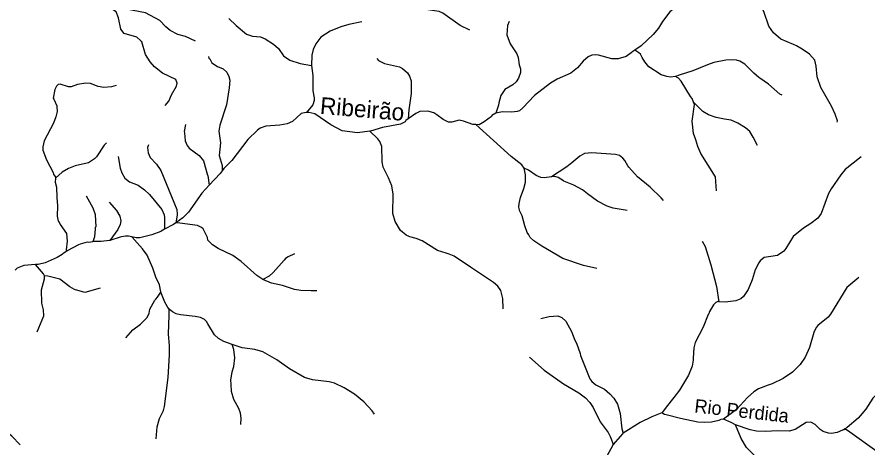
# Model space of a CAD drawing. Extents: x 280.4 to 335.6, y 8893.9 to 8949.5.
# Drawn here: x 314.12 to 324.16, y 8938.13 to 8943.22 of the extents above; entities that cross this region are included whole.
import ezdxf
from ezdxf.enums import TextEntityAlignment as Align

# ---------------------------------------------------------------- set-up
doc = ezdxf.new("R2010")
doc.units = 0
doc.header["$LTSCALE"] = 0.064
doc.layers.add('61', color=7, linetype='Continuous')
doc.layers.add('7', color=7, linetype='Continuous', lineweight=25)

msp = doc.modelspace()

# ---------------------------------------------------------------- linework, layer by layer
at = {"layer": '7'}
for p, q in [((318.2905, 8941.869), (318.2847, 8941.8682)), ((321.1556, 8938.1677), (321.0782, 8938.0222))]:
    msp.add_line(p, q, dxfattribs=at)
for points in [[(319.4625, 8943.0629), (319.3518, 8943.1173), (319.1473, 8943.2634), (319.1022, 8943.2832), (318.9404, 8943.3071), (318.7025, 8943.4163), (318.5373, 8943.5115), (318.373, 8943.6324), (318.2894, 8943.7208), (318.231, 8943.8085), (318.1513, 8943.983), (318.0958, 8944.0646), (318.0478, 8944.1159), (317.9296, 8944.1715), (317.8394, 8944.2139), (317.7235, 8944.2382), (317.638, 8944.2668), (317.5637, 8944.3067), (317.4833, 8944.3597), (317.3938, 8944.4325), (317.339, 8944.4902), (317.2758, 8944.5371), (317.1869, 8944.5672), (317.1169, 8944.5733)], [(322.6434, 8943.6376), (322.6119, 8943.6257), (322.3545, 8943.5073), (322.2424, 8943.4828), (322.1242, 8943.4758), (322.0597, 8943.4596), (321.9757, 8943.3812), (321.86, 8943.3071), (321.8269, 8943.2788), (321.7395, 8943.1632), (321.6899, 8943.0842), (321.6293, 8943.0127), (321.4863, 8942.8786), (321.4133, 8942.8255)], [(323.8022, 8941.9733), (323.8031, 8941.989), (323.7758, 8942.0709), (323.7336, 8942.1648), (323.6086, 8942.3833), (323.5647, 8942.5098), (323.5519, 8942.6364), (323.5385, 8942.7064), (323.4744, 8942.7782), (323.3888, 8942.837), (323.3192, 8942.8762), (323.2872, 8942.8942), (323.1369, 8942.9566), (323.0483, 8943.029), (322.9955, 8943.1073), (322.9365, 8943.2824), (322.8647, 8943.4233), (322.7805, 8943.5268), (322.7373, 8943.5683), (322.6434, 8943.6376)], [(315.8656, 8942.1736), (315.9103, 8942.2247), (315.9433, 8942.2985), (316.0031, 8942.4007), (316.0096, 8942.4356), (315.9942, 8942.4776), (315.8362, 8942.552), (315.7422, 8942.6281), (315.6891, 8942.6896), (315.6344, 8942.774), (315.5908, 8942.9225), (315.5797, 8942.9304), (315.5772, 8942.9417), (315.5316, 8942.9777), (315.384, 8943.022), (315.3445, 8943.0745), (315.3159, 8943.2089), (315.2875, 8943.2772), (315.2205, 8943.3235)], [(316.2248, 8942.9325), (316.1083, 8942.986), (316.0188, 8943.01), (315.9273, 8943.0573), (315.8761, 8943.102), (315.8046, 8943.1779), (315.6348, 8943.2664), (315.4054, 8943.3088), (315.3485, 8943.3361), (315.3039, 8943.3541)], [(316.6187, 8943.2005), (316.7038, 8943.1153), (316.8267, 8943.0132), (316.9, 8942.9893), (316.9934, 8942.9851), (317.0488, 8942.9589), (317.1475, 8942.8973), (317.2056, 8942.8455), (317.2658, 8942.7583), (317.3411, 8942.7088), (317.4599, 8942.6662), (317.5937, 8942.6439)], [(318.1879, 8943.1595), (318.0377, 8943.1295), (317.9411, 8943.1006), (317.8163, 8943.0508), (317.7071, 8942.9797), (317.6453, 8942.9023), (317.6142, 8942.8328), (317.5996, 8942.7667), (317.5937, 8942.6439)], [(319.9277, 8943.1661), (319.9093, 8943.1169), (319.9028, 8943.0058), (319.9401, 8942.9007), (320.021, 8942.7836), (320.0351, 8942.7394), (320.0478, 8942.6513), (320.0608, 8942.6051), (320.0624, 8942.5603), (320.0375, 8942.4945), (320.0096, 8942.4516), (319.9701, 8942.4168), (319.8789, 8942.3608), (319.8309, 8942.2906), (319.8056, 8942.2044), (319.8039, 8942.176), (319.7727, 8942.0796)], [(321.4133, 8942.8255), (321.389, 8942.8081), (321.3698, 8942.793), (321.3108, 8942.752), (321.2144, 8942.7232), (321.1403, 8942.7251), (320.9827, 8942.7685), (320.9448, 8942.7717), (320.9031, 8942.7666), (320.8599, 8942.747), (320.8017, 8942.6967), (320.7338, 8942.6159), (320.6557, 8942.5541), (320.4962, 8942.4846), (320.4164, 8942.4359), (320.2266, 8942.2912), (320.0901, 8942.1452), (320.0491, 8942.1102), (320.0238, 8942.0999), (319.9607, 8942.0934), (319.8518, 8942.0968), (319.7727, 8942.0796)], [(321.8922, 8942.5132), (321.8314, 8942.508), (321.788, 8942.5127), (321.7245, 8942.5325), (321.5786, 8942.6291), (321.5294, 8942.6861), (321.5, 8942.7405), (321.4775, 8942.7769), (321.4601, 8942.796), (321.4133, 8942.8255)], [(316.3799, 8942.7512), (316.3817, 8942.7325), (316.393, 8942.725), (316.4195, 8942.6773), (316.4865, 8942.6339), (316.553, 8942.6038), (316.5947, 8942.5641), (316.619, 8942.5155), (316.6302, 8942.47), (316.6238, 8942.3812), (316.5905, 8942.1804), (316.5135, 8941.9388), (316.5026, 8941.8669), (316.52, 8941.7319), (316.5057, 8941.583), (316.5389, 8941.4647), (316.5402, 8941.4281), (316.5411, 8941.4018)], [(318.3657, 8942.7284), (318.3861, 8942.7053), (318.4577, 8942.6699), (318.632, 8942.6276), (318.671, 8942.6099), (318.7292, 8942.5568), (318.7531, 8942.5179), (318.7701, 8942.4634), (318.7701, 8942.3148), (318.7443, 8942.1224), (318.7375, 8942.0144)], [(323.1511, 8942.294), (323.125, 8942.3063), (322.9915, 8942.423), (322.887, 8942.4951), (322.8773, 8942.5034), (322.8173, 8942.5547), (322.7095, 8942.6622), (322.6527, 8942.6941), (322.6106, 8942.7073), (322.554, 8942.7122), (322.4853, 8942.7076), (322.3446, 8942.6791), (322.2709, 8942.654), (322.0973, 8942.5798), (321.9352, 8942.5286), (321.8922, 8942.5132)], [(317.5937, 8942.6439), (317.6091, 8942.5251), (317.6092, 8942.3461), (317.6279, 8942.2624), (317.6283, 8942.2316), (317.6094, 8942.1804), (317.5345, 8942.0891)], [(322.1059, 8942.2101), (322.0901, 8942.2532), (322.07, 8942.2772), (321.9581, 8942.4594), (321.9269, 8942.4941), (321.8922, 8942.5132)], [(315.2896, 8942.4087), (315.2331, 8942.3909), (315.1416, 8942.383), (315.0783, 8942.3981), (314.987, 8942.4337), (314.9307, 8942.4354), (314.8329, 8942.4194), (314.7582, 8942.3927), (314.727, 8942.3908), (314.6267, 8942.4225), (314.6053, 8942.419), (314.5842, 8942.3997), (314.565, 8942.3596), (314.5468, 8942.2572), (314.555, 8942.2486), (314.5866, 8942.1662), (314.5929, 8942.0914), (314.5866, 8942.0872), (314.5764, 8942.0362), (314.551, 8941.9648), (314.4379, 8941.7559), (314.4236, 8941.6854), (314.4247, 8941.6428), (314.465, 8941.5288), (314.5435, 8941.3794), (314.5501, 8941.3548), (314.5733, 8941.3307), (314.5726, 8941.3123)], [(322.3756, 8941.1639), (322.3653, 8941.3282), (322.1913, 8941.6065), (322.1568, 8941.6876), (322.1306, 8941.7669), (322.1065, 8941.8399), (322.0904, 8941.9852), (322.1154, 8942.1841), (322.1059, 8942.2101)], [(322.8603, 8941.7006), (322.8099, 8941.799), (322.7678, 8941.865), (322.7197, 8941.9066), (322.6272, 8941.9632), (322.5476, 8941.9973), (322.4711, 8942.0108), (322.3727, 8942.0282), (322.2832, 8942.0624), (322.2162, 8942.1018), (322.1059, 8942.2101)], [(319.534, 8941.9455), (319.4995, 8941.9476), (319.3907, 8941.9861), (319.3402, 8941.9971), (319.2506, 8941.9752), (319.214, 8941.9753), (319.1507, 8942.0061), (319.0765, 8942.0633), (319.0381, 8942.0839), (318.9678, 8942.103), (318.8725, 8942.1015), (318.8277, 8942.0788), (318.7375, 8942.0144)], [(317.5345, 8942.0891), (317.5307, 8942.0892), (317.4717, 8942.0755), (317.3692, 8941.9846), (317.3084, 8941.9543), (317.2228, 8941.9392), (317.0542, 8941.9288), (316.9894, 8941.9049), (316.9567, 8941.8822), (316.8431, 8941.7718), (316.6543, 8941.524), (316.5587, 8941.4261), (316.5411, 8941.4018)], [(318.2847, 8941.8682), (318.1368, 8941.8471), (317.957, 8941.8714), (317.8213, 8941.9429), (317.6358, 8942.0718), (317.5639, 8942.0883), (317.5345, 8942.0891)], [(318.7375, 8942.0144), (318.7087, 8941.9938), (318.7027, 8941.98), (318.647, 8941.9516), (318.4351, 8941.9112), (318.2905, 8941.869)], [(319.7727, 8942.0796), (319.7243, 8942.054), (319.7193, 8942.0432), (319.6329, 8941.9772), (319.574, 8941.943), (319.534, 8941.9455)], [(316.1073, 8941.9487), (316.0914, 8941.8642), (316.0973, 8941.8486), (316.1038, 8941.7545), (316.1289, 8941.6985), (316.1519, 8941.6669), (316.2685, 8941.5802), (316.321, 8941.5172), (316.3683, 8941.3505), (316.3695, 8941.3429), (316.3879, 8941.2298)], [(320.1054, 8941.4329), (320.0768, 8941.4694), (319.9528, 8941.5676), (319.534, 8941.9455)], [(319.8565, 8939.7693), (319.853, 8939.892), (319.8294, 8939.9874), (319.7963, 8940.0357), (319.7447, 8940.0794), (319.4712, 8940.2618), (319.2793, 8940.3898), (319.2198, 8940.4146), (319.184, 8940.4258), (319.0835, 8940.4573), (318.9029, 8940.574), (318.8291, 8940.6008), (318.7558, 8940.6188), (318.712, 8940.64), (318.6472, 8940.6959), (318.5822, 8940.8028), (318.5549, 8940.8975), (318.5574, 8941.1241), (318.5425, 8941.2217), (318.505, 8941.3154), (318.4391, 8941.4448), (318.4312, 8941.5073), (318.4244, 8941.6878), (318.401, 8941.7472), (318.3783, 8941.7798), (318.2847, 8941.8682)], [(315.1761, 8941.7312), (315.1457, 8941.7021), (315.0551, 8941.564), (315.0325, 8941.5403), (314.9615, 8941.4938), (314.8033, 8941.4582), (314.7266, 8941.4293), (314.6512, 8941.3837), (314.5726, 8941.3123)], [(315.6688, 8941.707), (315.6594, 8941.6763), (315.6653, 8941.6136), (315.6904, 8941.5589), (315.7657, 8941.4768), (315.8146, 8941.4024), (316.0033, 8940.945), (316.0085, 8940.889), (316.0088, 8940.8855), (316.0097, 8940.8755), (315.9944, 8940.7866)], [(321.7523, 8941.0481), (321.7242, 8941.0819), (321.5939, 8941.2061), (321.4446, 8941.3301), (321.3395, 8941.4431), (321.3312, 8941.4572), (321.2938, 8941.5207), (321.2709, 8941.5484), (321.2293, 8941.5793), (321.185, 8941.5927), (320.9036, 8941.6119), (320.817, 8941.6043), (320.7629, 8941.5735), (320.6687, 8941.4956), (320.6111, 8941.4479), (320.4269, 8941.3276)], [(315.313, 8941.5711), (315.3355, 8941.4331), (315.3552, 8941.3746), (315.3925, 8941.3134), (315.4454, 8941.2682), (315.5486, 8941.23), (315.6249, 8941.1765), (315.6816, 8941.1214), (315.8265, 8940.9433), (315.8541, 8940.8795), (315.861, 8940.8466), (315.861, 8940.841), (315.8609, 8940.7099)], [(324.0822, 8941.567), (323.895, 8941.4176), (323.8431, 8941.3528), (323.7315, 8941.1887), (323.6992, 8941.1305), (323.6115, 8940.8968), (323.5717, 8940.8417), (323.4914, 8940.7784), (323.4017, 8940.7243), (323.2813, 8940.6248), (323.1956, 8940.484), (323.1692, 8940.4506), (323.0954, 8940.3982), (322.94, 8940.3741), (322.8929, 8940.3368), (322.8757, 8940.3139), (322.8342, 8940.2293), (322.7961, 8940.1107), (322.7514, 8939.9998), (322.6936, 8939.9157), (322.6629, 8939.8872), (322.6045, 8939.8622), (322.4789, 8939.8465), (322.4052, 8939.8536)], [(316.5411, 8941.4018), (316.5159, 8941.3668), (316.3879, 8941.2298)], [(320.9654, 8940.2479), (320.8063, 8940.2801), (320.5607, 8940.3648), (320.3156, 8940.5081), (320.2201, 8940.5735), (320.178, 8940.6136), (320.1593, 8940.6435), (320.1422, 8940.6707), (320.1123, 8940.7494), (320.0833, 8940.8677), (320.0513, 8940.9332), (320.0505, 8940.9379), (320.0446, 8940.9714), (320.0467, 8941.0151), (320.0639, 8941.0868), (320.1019, 8941.19), (320.1215, 8941.2656), (320.1215, 8941.3538), (320.1054, 8941.4329)], [(320.4269, 8941.3276), (320.3422, 8941.3182), (320.3039, 8941.3215), (320.2489, 8941.3452), (320.1577, 8941.4059), (320.1054, 8941.4329)], [(314.5726, 8941.3123), (314.5707, 8941.2658), (314.5845, 8941.2084), (314.5866, 8941.0834), (314.596, 8940.9874), (314.5931, 8940.8644), (314.6044, 8940.8062), (314.6124, 8940.8016), (314.6275, 8940.7677), (314.7016, 8940.6613), (314.7111, 8940.5701), (314.6985, 8940.4651), (314.7116, 8940.4566)], [(321.3201, 8940.9318), (321.1583, 8940.9606), (321.0844, 8940.982), (320.9703, 8941.0415), (320.854, 8941.1298), (320.7953, 8941.1744), (320.692, 8941.2292), (320.5753, 8941.2793), (320.5684, 8941.2823), (320.5069, 8941.3209), (320.4669, 8941.332), (320.4269, 8941.3276)], [(316.3879, 8941.2298), (316.3005, 8941.1363), (316.142, 8940.9105), (316.0754, 8940.8444), (316.033, 8940.8141), (315.9944, 8940.7866)], [(314.9364, 8941.1027), (315.0153, 8940.9636), (315.0421, 8940.885), (315.0471, 8940.74), (315.041, 8940.7317), (315.0391, 8940.6486), (315.0314, 8940.6387), (315.0319, 8940.6351), (315.0341, 8940.6196), (315.0152, 8940.5612)], [(315.2051, 8941.0313), (315.2934, 8940.9322), (315.3328, 8940.8648), (315.3444, 8940.809), (315.3358, 8940.7674), (315.3098, 8940.7079), (315.215, 8940.5783)], [(315.9944, 8940.7866), (315.9677, 8940.7675), (315.8609, 8940.7099)], [(317.0202, 8940.1152), (316.949, 8940.1624), (316.7637, 8940.3304), (316.6677, 8940.3993), (316.4951, 8940.4809), (316.4264, 8940.5265), (316.3731, 8940.5824), (316.3675, 8940.6114), (316.3167, 8940.7147), (316.2945, 8940.7323), (316.2482, 8940.7533), (316.0417, 8940.7804), (315.9944, 8940.7866)], [(315.8609, 8940.7099), (315.8206, 8940.6882), (315.8179, 8940.6816), (315.7099, 8940.6431), (315.5676, 8940.6077), (315.5259, 8940.61), (315.4731, 8940.6207)], [(315.4731, 8940.6207), (315.4344, 8940.6286), (315.3982, 8940.6299), (315.3511, 8940.6205), (315.3349, 8940.6172), (315.215, 8940.5783)], [(315.8167, 8939.9671), (315.8155, 8939.97), (315.7993, 8940.0548), (315.7563, 8940.1455), (315.722, 8940.251), (315.654, 8940.4029), (315.5984, 8940.4798), (315.4731, 8940.6207)], [(315.0152, 8940.5612), (314.9644, 8940.5529), (314.9479, 8940.5577), (314.8648, 8940.534), (314.8451, 8940.524), (314.7116, 8940.4566)], [(315.215, 8940.5783), (315.2119, 8940.5779), (315.1116, 8940.5635), (315.03, 8940.5636), (315.0152, 8940.5612)], [(322.2089, 8940.5674), (322.2422, 8940.5067), (322.3091, 8940.2901), (322.3781, 8940.0335), (322.4052, 8939.8536)], [(314.7116, 8940.4566), (314.6609, 8940.4175), (314.6499, 8940.4111), (314.5921, 8940.3774), (314.4504, 8940.3119), (314.3667, 8940.2947), (314.3385, 8940.2922)], [(317.3943, 8940.4185), (317.3203, 8940.3848), (317.2877, 8940.3626), (317.2713, 8940.3439), (317.1424, 8940.197), (317.0933, 8940.1546), (317.0202, 8940.1152)], [(314.3385, 8940.2922), (314.2003, 8940.2798), (314.1203, 8940.2519), (314.0974, 8940.2274)], [(314.444, 8940.1598), (314.4315, 8940.1821), (314.3385, 8940.2922)], [(314.3551, 8939.4976), (314.4346, 8939.6855), (314.4296, 8939.7559), (314.4103, 8939.838), (314.4092, 8939.9958), (314.4425, 8940.1231), (314.444, 8940.1598)], [(315.0991, 8940.0144), (314.9188, 8939.9634), (314.7983, 8939.9965), (314.7413, 8940.0279), (314.6257, 8940.1216), (314.4817, 8940.1564), (314.444, 8940.1598)], [(317.6563, 8939.9818), (317.5893, 8939.9838), (317.471, 8939.9872), (317.3937, 8939.9995), (317.252, 8940.0463), (317.1229, 8940.0735), (317.0202, 8940.1152)], [(324.0565, 8940.1385), (323.9168, 8940.0231), (323.7231, 8939.7057), (323.693, 8939.6725), (323.5717, 8939.5718), (323.554, 8939.5479), (323.5269, 8939.4881), (323.4738, 8939.3145), (323.422, 8939.198), (323.3643, 8939.1134), (323.2715, 8939.0223), (323.1625, 8938.9482), (323.0322, 8938.8843), (322.9853, 8938.8664), (322.8714, 8938.8231), (322.8154, 8938.7888), (322.7412, 8938.7237), (322.6124, 8938.5807), (322.4572, 8938.4646)], [(314.1567, 8938.1618), (314.0584, 8938.2667), (313.9884, 8938.3254), (313.9111, 8938.4053), (313.8787, 8938.4679), (313.8636, 8938.5565), (313.8573, 8938.6405), (313.8716, 8938.9404), (313.8667, 8939.0203), (313.8149, 8939.1178), (313.6942, 8939.2371), (313.6495, 8939.3283), (313.6447, 8939.369), (313.6493, 8939.4305), (313.6621, 8939.489), (313.7648, 8939.7623), (313.7928, 8939.8547), (313.7928, 8939.8924), (313.7713, 8939.9729)], [(315.4016, 8939.4269), (315.4874, 8939.5222), (315.5756, 8939.5883), (315.6564, 8939.6689), (315.6767, 8939.7165), (315.686, 8939.7646), (315.746, 8939.8719), (315.757, 8939.8839), (315.7783, 8939.9072), (315.8167, 8939.9671)], [(315.9146, 8939.7667), (315.8974, 8939.7872), (315.8779, 8939.8218), (315.8654, 8939.8501), (315.8167, 8939.9671)], [(322.4052, 8939.8536), (322.3917, 8939.8549), (322.3697, 8939.8462), (322.3393, 8939.8185), (322.292, 8939.7375), (322.2857, 8939.7086), (322.2774, 8939.7032), (322.2172, 8939.5521), (322.1241, 8939.3721), (322.1104, 8939.3087), (322.1018, 8939.1875), (322.1, 8939.162), (322.0876, 8939.0929), (322.0462, 8938.9859), (321.9395, 8938.8078), (321.8726, 8938.7225), (321.7828, 8938.6079), (321.7501, 8938.5662), (321.7305, 8938.5412)], [(315.7604, 8938.2329), (315.7718, 8938.3766), (315.799, 8938.4733), (315.8466, 8938.5686), (315.8612, 8938.6172), (315.9011, 8938.9563), (315.9172, 8939.2276), (315.9171, 8939.3355), (315.9077, 8939.4699), (315.9129, 8939.6946), (315.9146, 8939.7667)], [(316.657, 8939.3495), (316.5584, 8939.3835), (316.4955, 8939.4182), (316.4492, 8939.4629), (316.3717, 8939.5915), (316.3542, 8939.6201), (316.3316, 8939.6439), (316.2851, 8939.6676), (316.2206, 8939.6795), (316.0473, 8939.6983), (315.9967, 8939.7113), (315.9537, 8939.7321), (315.9146, 8939.7667)], [(320.3028, 8939.6555), (320.4007, 8939.6788), (320.5045, 8939.685), (320.5485, 8939.6672), (320.598, 8939.6239), (320.6653, 8939.5025), (320.7037, 8939.3977), (320.7231, 8939.3644), (320.7669, 8939.2425), (320.7698, 8939.2197), (320.8797, 8938.9428), (320.9042, 8938.9119), (320.9506, 8938.8732), (321.0526, 8938.82), (321.1168, 8938.7663), (321.1626, 8938.7141), (321.1627, 8938.7139), (321.2058, 8938.6421), (321.2375, 8938.5316), (321.2587, 8938.351), (321.2725, 8938.2989)], [(316.7616, 8938.4013), (316.7646, 8938.4792), (316.7566, 8938.538), (316.739, 8938.5909), (316.68, 8938.6982), (316.651, 8938.7939), (316.646, 8938.8791), (316.6432, 8938.9261), (316.6603, 8939.0268), (316.6786, 8939.0881), (316.6894, 8939.1912), (316.6895, 8939.1922), (316.6784, 8939.2876), (316.657, 8939.3495)], [(318.3407, 8938.5247), (318.3126, 8938.5633), (318.2131, 8938.6698), (318.1017, 8938.762), (317.9824, 8938.8361), (317.8668, 8938.8917), (317.8029, 8938.9062), (317.6075, 8938.9287), (317.5138, 8938.9569), (317.3341, 8939.0605), (317.186, 8939.1678), (317.0223, 8939.2618), (316.9246, 8939.2882), (316.7778, 8939.3101), (316.7663, 8939.3118), (316.657, 8939.3495)], [(320.1685, 8939.1982), (320.3411, 8939.0434), (320.5706, 8938.8828), (320.7512, 8938.7756), (320.8316, 8938.7178), (320.8796, 8938.6629), (320.9208, 8938.6043), (321.0022, 8938.4341), (321.0962, 8938.3067), (321.1214, 8938.2608), (321.136, 8938.2236), (321.1479, 8938.192), (321.1556, 8938.1677)], [(324.7653, 8938.777), (324.6132, 8938.7972), (324.5019, 8938.7957), (324.4379, 8938.8051), (324.3637, 8938.8003), (324.2998, 8938.7824), (324.2675, 8938.7627), (324.2232, 8938.7151), (324.1373, 8938.5846), (324.0472, 8938.4785), (323.9198, 8938.3687), (323.8651, 8938.3368)], [(321.7305, 8938.5412), (321.6136, 8938.495), (321.4736, 8938.4266), (321.2725, 8938.2989)], [(322.4572, 8938.4646), (322.428, 8938.4624), (322.4051, 8938.4511), (322.3172, 8938.429), (322.2355, 8938.4247), (322.155, 8938.4294), (321.9518, 8938.4729), (321.7825, 8938.5166), (321.7622, 8938.5219), (321.7305, 8938.5412)], [(322.6008, 8938.3979), (322.5505, 8938.4262), (322.4572, 8938.4646)], [(323.8651, 8938.3368), (323.8004, 8938.3066), (323.7328, 8938.2969), (323.6984, 8938.3002), (323.6337, 8938.3215), (323.6018, 8938.3421), (323.54, 8938.401), (323.4902, 8938.429), (323.433, 8938.4257), (323.304, 8938.3423), (323.2329, 8938.324), (323.099, 8938.3287), (322.9523, 8938.3207), (322.8481, 8938.3235), (322.774, 8938.3401), (322.6008, 8938.3979)], [(324.3247, 8936.7933), (324.2839, 8936.8741), (324.2316, 8936.9501), (324.123, 8937.0588), (324.0994, 8937.0913), (324.0374, 8937.2065), (323.9741, 8937.2603), (323.8223, 8937.3458), (323.7861, 8937.3561), (323.6088, 8937.3468), (323.5223, 8937.3626), (323.4581, 8937.4067), (323.2859, 8937.5679), (323.238, 8937.6015), (323.0515, 8937.7322), (322.9671, 8937.8387), (322.9325, 8937.9103), (322.8823, 8937.9794), (322.7308, 8938.1293), (322.6665, 8938.2375), (322.6008, 8938.3979)], [(321.2725, 8938.2989), (321.2653, 8938.2943), (321.1556, 8938.1677)], [(324.8814, 8937.8231), (324.8032, 8937.88), (324.7177, 8937.9141), (324.6843, 8937.9191), (324.6259, 8937.9161), (324.5684, 8937.9258), (324.4834, 8937.9542), (324.4232, 8937.9849), (324.2982, 8938.0651), (323.9242, 8938.3332), (323.9035, 8938.3428), (323.8651, 8938.3368)]]:
    msp.add_lwpolyline(points, dxfattribs=at)

# ---------------------------------------------------------------- texts
at = {"layer": '61'}
for s, height, rotation, p in [('Ribeirão', 0.2, 355.236, (318.1857, 8942.0319)), ('Rio Perdida', 0.16, 353.66, (322.6652, 8938.4841))]:
    msp.add_text(s, height=height, rotation=rotation, dxfattribs=at).set_placement(p, align=Align.CENTER)

doc.saveas('drawing.dxf')
